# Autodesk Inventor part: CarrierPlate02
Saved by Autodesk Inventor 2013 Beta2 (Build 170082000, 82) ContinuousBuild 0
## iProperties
Created: 2008-02
Part Number: CarrierPlate02
Document SubType Name: Modeling
Designer: grh
Density: 1 g/cm^3
Material: Generic
Author: grh
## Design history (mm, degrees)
sketch "Sketch1"
  geometry: L1 (48.514, 0)-(0, 0); L2 (0, 0)-(37.164, 31.184); C1 r 53.34 at (0, 0)
  constraints: 4 end point, 1 centre point, 1 equal length, 1 horizontal, 1 other
  dimensions: "BlankDiameter" = 106.68 diameter of C1; "PlanetRadius" = 48.514 distance of L1.start L1.end; "Angle1" = 40 deg angle of L2 L1
extrude "Extrusion1" new body sketch "Sketch1" stored distance "d9" = 13.97; taper "d10" = 0 deg
node "Axis1"
node "Axis2"
node "Axis3"
body "Solid1"
